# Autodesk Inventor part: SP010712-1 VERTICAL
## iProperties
Created: 2013-01
Part Number: SP010712-1 VERTICAL
Material: Aluminum-6061
Description: PROFILE 45X45 UL
Document SubType Name: Modeling
Designer: Administrator
Stock Number: 20.1063 PROFILE 45X45 UL
Density: 2.71 g/cm^3
FINISH: CLEAR ANODIZED
Author: Administrator
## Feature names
1. Extrusion1
